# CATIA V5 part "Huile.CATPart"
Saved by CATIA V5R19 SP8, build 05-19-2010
Part number: Huile
Bounding box of the stored display mesh (mm): x -5.773 to 5.773, y -5.763 to 5.763, z -169.7 to 0
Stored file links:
  D:\Documents\1_Travail\1 - ac-limoges.fr\OneDrive - ac-limoges.fr\STI2D_Turgot\2 -2I2D\3_SEQUENCE_Serre_Connectée\3- Spécificités\ITEC\EC 3 Ouverture automatique\Simulation  Ouverture Automatique\Huile.CATPart
  D:\Documents\1_Travail\1 - ac-limoges.fr\OneDrive - ac-limoges.fr\STI2D_Turgot\2 -2I2D\3_SEQUENCE_Serre_Connectée\Dossier technique_SERRE\Maquettes_CATIA\Ouverture_Automatique_ACD\Verin thermodynamique.CATProduct
  D:\Documents\1_Travail\1 - ac-limoges.fr\OneDrive - ac-limoges.fr\STI2D_Turgot\2 -2I2D\3_SEQUENCE_Serre_Connectée\Dossier technique_SERRE\Maquettes_CATIA\Ouverture_automatique_ACD_Corrigé\Tete_de_verin.CATPart
  D:\Documents\1_Travail\1 - ac-limoges.fr\OneDrive - ac-limoges.fr\STI2D_Turgot\2 -2I2D\3_SEQUENCE_Serre_Connectée\3- Spécificités\ITEC\EC 3 Ouverture automatique\Simulation  Ouverture Automatique\Tige_de_verin.CATPart
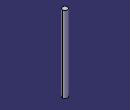
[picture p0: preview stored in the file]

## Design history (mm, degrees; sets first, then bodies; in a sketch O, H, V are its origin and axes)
AxisSystem1: origin (0, 0, 0), X (1, 0, 0), Y (0, 1, 0), Z (0, 0, 1)
Set1
  DatumSurface1: linked copy from another document
Body1 (main body)
  Sketch1 on XY plane of AxisSystem1, origin (0, 0, 0), H (1, 0, 0), V (0, 1, 0)
    circle A1 centre (0, 0) radius 5.773
    radius A1 = 5.773
  Pad1: profile Sketch1, direction (0, 0, 1), up to face of DatumSurface1
  Body2 "NONE"
    Solid1: linked copy from another document
  Remove1: tool Body2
